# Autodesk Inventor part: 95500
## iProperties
Author: Administrator
Shininess: 64.0
Angle Display Precision: 2
Document Length Units: 11272
Document Angle Units: 11286
Document Time Units: 11279
Document Mass Units: 11290
Document Length Units Precision: 3
Document Angle Units Precision: 2
Compacted: True
PropertySet Name: _Private Model Information
Created: 2002-04
Part Number: 95500
Material: ASTM A36 HRS
Document SubType Name: Modeling
Designer: Administrator
Control State: 0
Master: False
Checked Out: False
PropertySet Name: Design Tracking Control
Density: 0.0
Volumn: 0.0
Area: 0.0
PropertySet Name: Model Information
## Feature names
1. Revolution1
